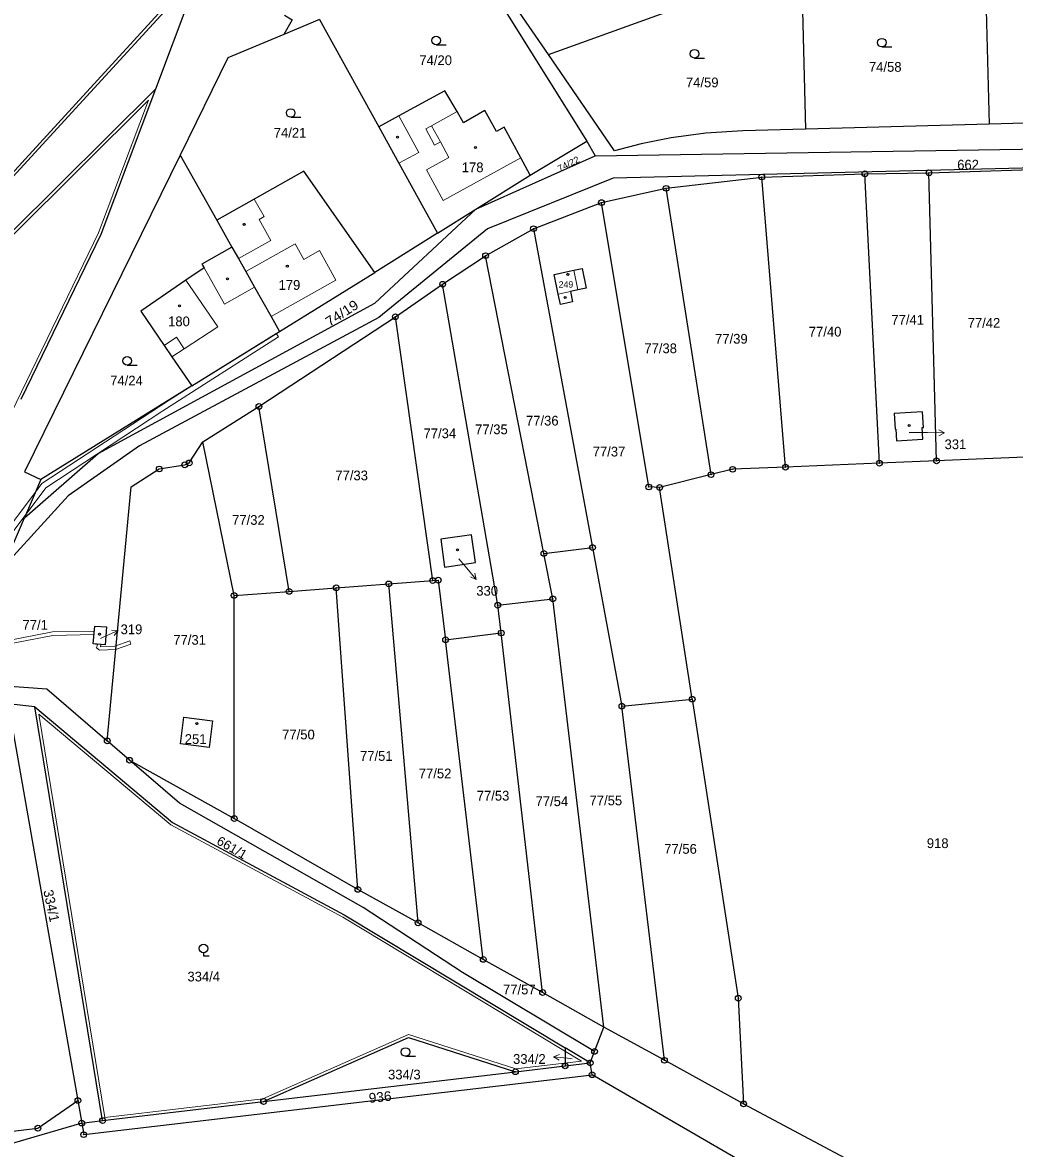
# Model space of a CAD drawing. Extents: x -758887 to -754328, y -1031688 to -1029144.
# Drawn here: x -756593.9 to -756420.8, y -1030846 to -1030649.6 of the extents above; entities that cross this region are included whole.
import ezdxf
from ezdxf.enums import TextEntityAlignment as Align

# ---------------------------------------------------------------- set-up
doc = ezdxf.new("R2010")
doc.units = 0
doc.header["$LTSCALE"] = 0.68
for name, color, linetype, lineweight in [('1', 7, 'Continuous', 25), ('13', 7, 'Continuous', 13), ('3', 7, 'Continuous', 25), ('4', 7, 'Continuous', 13), ('5', 7, 'Continuous', 25), ('7', 7, 'Continuous', 13), ('8', 7, 'Continuous', 25)]:
    doc.layers.add(name, color=color, linetype=linetype, lineweight=lineweight)
doc.layers.add('2', color=7, linetype='Continuous')

msp = doc.modelspace()

# ---------------------------------------------------------------- linework, layer by layer
at = {"layer": '1'}
for p, q in [((-756426.06, -1030637.12), (-756425.23, -1030667.33)), ((-756457.99, -1030641.12), (-756457.25, -1030668.21)), ((-756570.62, -1030661.18), (-756563.65, -1030642.64)), ((-756542.09, -1030649.11), (-756548.27, -1030651.69)), ((-756542.09, -1030649.11), (-756531.73, -1030667.81)), ((-756505.29, -1030676.26), (-756495.42, -1030670.29)), ((-756514.77, -1030682.19), (-756493.95, -1030672.9)), ((-756460.76, -1030727.18), (-756464.91, -1030676.57)), ((-756444.38, -1030726.5), (-756446.91, -1030676.02)), ((-756434.41, -1030726.09), (-756435.73, -1030675.84)), ((-756473.76, -1030728.49), (-756481.59, -1030678.54)), ((-756521.45, -1030686.37), (-756532.44, -1030693.24)), ((-756504.73, -1030685.58), (-756494.43, -1030741.22)), ((-756502.92, -1030742.22), (-756513.09, -1030690.29)), ((-756549.05, -1030703.54), (-756532.44, -1030693.24)), ((-756510.97, -1030751.27), (-756520.58, -1030695.27)), ((-756564.31, -1030713), (-756549.05, -1030703.54)), ((-756564.31, -1030713), (-756590.69, -1030729.36)), ((-756562.42, -1030722.77), (-756552.63, -1030716.6)), ((-756556.96, -1030749.57), (-756562.42, -1030722.77)), ((-756444.38, -1030726.5), (-756460.76, -1030727.18)), ((-756590.69, -1030729.36), (-756593.53, -1030736.02)), ((-756579.1, -1030774.93), (-756574.95, -1030730.63)), ((-756597.17, -1030744.56), (-756593.53, -1030736.02)), ((-756502.92, -1030742.22), (-756494.43, -1030741.22)), ((-756494.43, -1030741.22), (-756489.31, -1030768.85)), ((-756539.14, -1030748.23), (-756529.98, -1030747.55)), ((-756524.87, -1030806.67), (-756529.98, -1030747.55)), ((-756547.36, -1030748.85), (-756539.14, -1030748.23)), ((-756535.37, -1030800.83), (-756539.14, -1030748.23)), ((-756492.45, -1030824.84), (-756501.36, -1030750.16)), ((-756513.49, -1030813.05), (-756520.07, -1030757.28)), ((-756503.14, -1030818.82), (-756510.35, -1030756.11)), ((-756596.41, -1030768.46), (-756584.22, -1030837.68)), ((-756591.74, -1030769.01), (-756596.41, -1030768.46)), ((-756579.91, -1030841.16), (-756591.74, -1030769.01)), ((-756481.89, -1030830.65), (-756489.31, -1030768.85)), ((-756575.2, -1030778.3), (-756579.1, -1030774.93)), ((-756535.37, -1030800.83), (-756556.93, -1030788.48)), ((-756524.87, -1030806.67), (-756535.37, -1030800.83)), ((-756513.49, -1030813.05), (-756524.87, -1030806.67)), ((-756494.84, -1030831.1), (-756499.23, -1030828.46)), ((-756499.23, -1030828.46), (-756499.2, -1030831.62)), ((-756494.84, -1030831.1), (-756494.08, -1030829.1)), ((-756507.88, -1030832.64), (-756499.2, -1030831.62)), ((-756499.2, -1030831.62), (-756494.84, -1030831.1)), ((-756551.82, -1030837.84), (-756507.88, -1030832.64)), ((-756468.05, -1030848.51), (-756494.5, -1030833.17)), ((-756579.91, -1030841.16), (-756551.82, -1030837.84)), ((-756468.07, -1030838.25), (-756377.14, -1030886.55))]:
    msp.add_line(p, q, dxfattribs=at)
for points in [[(-756312.59, -1030555.25), (-756315.52, -1030551.79), (-756381.49, -1030591.35), (-756401.18, -1030595.86), (-756437.11, -1030607.98), (-756464.98, -1030615.64), (-756516.89, -1030636.06), (-756515.63, -1030638.06), (-756495.42, -1030670.29), (-756493.95, -1030672.9)], [(-756502.13, -1030655.2), (-756514.55, -1030637.12), (-756496.93, -1030629.62), (-756473.6, -1030620.91)], [(-756502.13, -1030655.2), (-756465.93, -1030642.12), (-756473.6, -1030620.91)], [(-756622.25, -1030695.77), (-756617.82, -1030689.9), (-756596.84, -1030677.93), (-756567.17, -1030645.53)], [(-756548.16, -1030648.36), (-756546.86, -1030649.18), (-756548.27, -1030651.69)], [(-756493.95, -1030672.9), (-756371.38, -1030670.94), (-756309.15, -1030664.75), (-756283.71, -1030651.34)], [(-756548.27, -1030651.69), (-756558.05, -1030655.77), (-756566.39, -1030672.73), (-756559.98, -1030684.11)], [(-756282.9, -1030655.55), (-756308.06, -1030668.02), (-756379, -1030674.01), (-756490.83, -1030676.79), (-756512.76, -1030685.59), (-756531.71, -1030701.08), (-756573.47, -1030723.47), (-756585.94, -1030732.18), (-756597.17, -1030744.56)], [(-756457.25, -1030668.21), (-756468.21, -1030668.51), (-756474.65, -1030668.92), (-756480.7, -1030669.74), (-756485.92, -1030670.8), (-756490.57, -1030672.03), (-756502.13, -1030655.2)], [(-756300.24, -1030658.53), (-756307.58, -1030661.72), (-756313.13, -1030663.29), (-756320.52, -1030664.4), (-756327.16, -1030664.64), (-756346.44, -1030665.17), (-756369.47, -1030665.8), (-756396.2, -1030666.53), (-756425.23, -1030667.33), (-756457.25, -1030668.21)], [(-756570.62, -1030661.18), (-756595.91, -1030686.32), (-756615.43, -1030693.08), (-756624.55, -1030704.88), (-756623.32, -1030705.86)], [(-756594.09, -1030715.3), (-756580.15, -1030686.52), (-756570.62, -1030661.18)], [(-756505.29, -1030676.26), (-756506.93, -1030673.25), (-756509.87, -1030667.89), (-756511.21, -1030668.63), (-756513.21, -1030664.99), (-756516.96, -1030667.14), (-756518.04, -1030665.15), (-756520.2, -1030661.55), (-756528.2, -1030665.9), (-756531.73, -1030667.81)], [(-756531.73, -1030667.81), (-756528.22, -1030674.15), (-756521.45, -1030686.37), (-756514.77, -1030682.19), (-756505.29, -1030676.26)], [(-756566.39, -1030672.73), (-756593.55, -1030728.01), (-756590.69, -1030729.36)], [(-756552.63, -1030716.6), (-756528.83, -1030700.94), (-756520.58, -1030695.27), (-756513.09, -1030690.29), (-756504.73, -1030685.58), (-756492.87, -1030681.04), (-756481.59, -1030678.54), (-756464.91, -1030676.57), (-756446.91, -1030676.02), (-756435.73, -1030675.84), (-756417.72, -1030675.24), (-756398.55, -1030674.79), (-756378.46, -1030674.21), (-756358.59, -1030673.95), (-756338.15, -1030673.21), (-756319.23, -1030673.82)], [(-756532.44, -1030693.24), (-756544.82, -1030675.57), (-756553.45, -1030680.43), (-756559.98, -1030684.11), (-756557.34, -1030688.81)], [(-756482.72, -1030730.71), (-756484.63, -1030730.64), (-756492.87, -1030681.04)], [(-756593.53, -1030736.02), (-756580.68, -1030724.81), (-756532.4, -1030698.57), (-756514.77, -1030682.19)], [(-756557.34, -1030688.81), (-756562.57, -1030691.75), (-756562.19, -1030692.42), (-756565.37, -1030694.59), (-756573.24, -1030699.98), (-756569.15, -1030705.95), (-756567.8, -1030707.92), (-756564.31, -1030713)], [(-756557.34, -1030688.81), (-756556.21, -1030690.81), (-756554.94, -1030693.08), (-756553.41, -1030695.78), (-756550.52, -1030700.93), (-756549.05, -1030703.54)], [(-756529.98, -1030747.55), (-756522.31, -1030746.97), (-756528.83, -1030700.94)], [(-756556.96, -1030749.57), (-756547.36, -1030748.85), (-756552.63, -1030716.6)], [(-756574.95, -1030730.63), (-756570.02, -1030727.5), (-756565.58, -1030726.78), (-756564.78, -1030726.44), (-756562.42, -1030722.77)], [(-756415.17, -1030725.25), (-756416.23, -1030725.34), (-756434.41, -1030726.09), (-756444.38, -1030726.5)], [(-756460.76, -1030727.18), (-756469.98, -1030727.56), (-756473.76, -1030728.49), (-756482.72, -1030730.71)], [(-756489.31, -1030768.85), (-756477.04, -1030767.65), (-756482.72, -1030730.71)], [(-756510.97, -1030751.27), (-756501.36, -1030750.16), (-756502.92, -1030742.22)], [(-756522.31, -1030746.97), (-756521.34, -1030746.9), (-756520.07, -1030757.28)], [(-756575.2, -1030778.3), (-756556.93, -1030788.48), (-756556.96, -1030749.57)], [(-756520.07, -1030757.28), (-756510.35, -1030756.11), (-756510.97, -1030751.27)], [(-756605.74, -1030764.66), (-756589.65, -1030765.83), (-756579.1, -1030774.93)], [(-756591.74, -1030769.01), (-756567.74, -1030789.14), (-756537.76, -1030805.25), (-756499.23, -1030828.46)], [(-756477.04, -1030767.65), (-756469.01, -1030819.82), (-756468.07, -1030838.25)], [(-756494.08, -1030829.1), (-756517.09, -1030815.34), (-756534.42, -1030804.01), (-756566.5, -1030785.8), (-756575.2, -1030778.3)], [(-756494.08, -1030829.1), (-756492.45, -1030824.84), (-756503.14, -1030818.82), (-756513.49, -1030813.05)], [(-756468.07, -1030838.25), (-756481.89, -1030830.65), (-756492.45, -1030824.84)], [(-756551.82, -1030837.84), (-756526.53, -1030826.65), (-756507.88, -1030832.64)], [(-756583.54, -1030841.59), (-756583.21, -1030843.62), (-756494.5, -1030833.17), (-756494.84, -1030831.1)], [(-756614.71, -1030845.27), (-756591.19, -1030842.49), (-756584.22, -1030837.68)], [(-756584.22, -1030837.68), (-756583.54, -1030841.59), (-756579.91, -1030841.16)], [(-756583.54, -1030841.59), (-756604.14, -1030847.6), (-756617.85, -1030857.11), (-756621.79, -1030861.59), (-756483.51, -1030902.61)]]:
    msp.add_lwpolyline(points, dxfattribs=at)
for points in [[(-756496.98, -1030696.27), (-756498.26, -1030696.56), (-756497.9, -1030698.32), (-756500.04, -1030698.8), (-756500.4, -1030697.03), (-756501.11, -1030693.56), (-756497.72, -1030692.83), (-756496.26, -1030692.51), (-756495.55, -1030695.95)], [(-756436.82, -1030722.3), (-756436.92, -1030720.28), (-756436.7, -1030720.27), (-756436.88, -1030717.52), (-756441.8, -1030717.8), (-756441.64, -1030720.54), (-756441.51, -1030720.54), (-756441.39, -1030722.59)], [(-756515.56, -1030738.96), (-756520.92, -1030739.74), (-756520.23, -1030744.6), (-756514.82, -1030743.82)], [(-756581.53, -1030758.02), (-756581.27, -1030754.91), (-756579.23, -1030755.06), (-756579.47, -1030758.15)], [(-756561.33, -1030776.08), (-756566.29, -1030775.42), (-756565.72, -1030770.81), (-756560.76, -1030771.42)]]:
    msp.add_lwpolyline(points, close=True, dxfattribs=at)
at = {"layer": '13'}
for points in [[(-756605.47, -1030751.56), (-756593.25, -1030735.36), (-756589.79, -1030730.78), (-756569.38, -1030717.35), (-756549.22, -1030704.47), (-756549.6, -1030703.88), (-756564.31, -1030713), (-756568.3, -1030715.47), (-756590.49, -1030730.04), (-756591.62, -1030731.54), (-756604.84, -1030749.06)], [(-756603.5, -1030759.41), (-756588.59, -1030756.52), (-756581.41, -1030756.38), (-756581.53, -1030758.02), (-756581.27, -1030754.91), (-756581.36, -1030755.78), (-756588.65, -1030755.92), (-756603.22, -1030758.75)]]:
    msp.add_lwpolyline(points, dxfattribs=at)
msp.add_lwpolyline([(-756581.53, -1030758.02), (-756580.8, -1030758.09), (-756580.96, -1030758.68), (-756580.47, -1030759.13), (-756577.66, -1030758.99), (-756574.98, -1030758.07), (-756575.18, -1030757.5), (-756577.78, -1030758.39), (-756580.25, -1030758.51), (-756580.19, -1030758.13), (-756579.47, -1030758.15)], close=True, dxfattribs=at)
at = {"layer": '3'}
for p, q in [((-756521.693, -1030653.5), (-756519.943, -1030653.5)), ((-756443.943, -1030653.88), (-756442.193, -1030653.88)), ((-756476.643, -1030655.81), (-756474.893, -1030655.81)), ((-756547.093, -1030666.15), (-756545.343, -1030666.15)), ((-756575.633, -1030709.38), (-756573.883, -1030709.38)), ((-756527.053, -1030829.95), (-756525.303, -1030829.95))]:
    msp.add_line(p, q, dxfattribs=at)
msp.add_lwpolyline([(-756562.32, -1030811.912), (-756562.32, -1030812.41), (-756561.319, -1030812.41)], dxfattribs=at)
for centre in [(-756521.6929, -1030652.7498), (-756443.9429, -1030653.1298), (-756476.6429, -1030655.0598), (-756547.0929, -1030665.3998), (-756575.6329, -1030708.6298), (-756562.3193, -1030811.1609), (-756527.0529, -1030829.1998)]:
    msp.add_circle(centre, 0.75, dxfattribs=at)
at = {"layer": '4'}
for p, q in [((-756597.16, -1030677.54), (-756568.24, -1030645.96)), ((-756595.64, -1030686.75), (-756571.9, -1030663.15)), ((-756580.61, -1030686.32), (-756571.9, -1030663.15)), ((-756524.75, -1030672.27), (-756528.2, -1030665.9)), ((-756522, -1030670.99), (-756523.51, -1030668.15)), ((-756520.97, -1030670.43), (-756522.52, -1030667.62)), ((-756528.22, -1030674.15), (-756524.75, -1030672.27)), ((-756523.42, -1030675.32), (-756519.49, -1030673.17)), ((-756551.73, -1030683.48), (-756553.45, -1030680.43)), ((-756597.65, -1030721.5), (-756580.61, -1030686.32)), ((-756556.21, -1030690.81), (-756550.55, -1030687.63)), ((-756554.94, -1030693.08), (-756546.31, -1030688.23)), ((-756546.31, -1030688.23), (-756544.79, -1030690.93)), ((-756544.79, -1030690.93), (-756542.08, -1030689.41)), ((-756542.08, -1030689.41), (-756539.19, -1030694.55)), ((-756562.19, -1030692.42), (-756558.64, -1030698.73)), ((-756497.72, -1030692.83), (-756496.98, -1030696.27)), ((-756559.8, -1030702.73), (-756565.37, -1030694.59)), ((-756539.19, -1030694.55), (-756550.52, -1030700.93)), ((-756558.64, -1030698.73), (-756553.41, -1030695.78)), ((-756500.4, -1030697.03), (-756498.26, -1030696.56)), ((-756569.15, -1030705.95), (-756567.03, -1030704.5)), ((-756565.65, -1030706.52), (-756559.8, -1030702.73)), ((-756568.02, -1030789.56), (-756591.03, -1030770.26)), ((-756579.49, -1030840.61), (-756591.03, -1030770.26)), ((-756526.56, -1030826.12), (-756551.95, -1030837.35)), ((-756507.83, -1030832.13), (-756526.56, -1030826.12)), ((-756579.49, -1030840.61), (-756551.95, -1030837.35))]:
    msp.add_line(p, q, dxfattribs=at)
for points in [[(-756523.51, -1030668.15), (-756522.52, -1030667.62), (-756518.04, -1030665.15)], [(-756519.49, -1030673.17), (-756520.97, -1030670.43), (-756522, -1030670.99)], [(-756523.42, -1030675.32), (-756520.49, -1030680.67), (-756506.93, -1030673.25)], [(-756550.55, -1030687.63), (-756552.6, -1030683.97), (-756551.73, -1030683.48)], [(-756567.8, -1030707.92), (-756565.65, -1030706.52), (-756567.03, -1030704.5)], [(-756507.83, -1030832.13), (-756496.35, -1030830.78), (-756538.01, -1030805.68), (-756568.02, -1030789.56)]]:
    msp.add_lwpolyline(points, dxfattribs=at)
at = {"layer": '5'}
for centre in [(-756528.4768, -1030669.6392), (-756514.8568, -1030671.4192), (-756555.1868, -1030684.8292), (-756547.6768, -1030692.1092), (-756558.1268, -1030694.3392), (-756498.7468, -1030693.5492), (-756499.1968, -1030697.5692), (-756566.4868, -1030699.0492), (-756439.2068, -1030719.9292), (-756517.9668, -1030741.6192), (-756580.4368, -1030756.3392), (-756563.4568, -1030771.9192)]:
    msp.add_circle(centre, 0.175, dxfattribs=at)
at = {"layer": '7'}
for p, q in [((-756433.009, -1030721.212), (-756434.002, -1030720.694)), ((-756514.711, -1030746.769), (-756514.971, -1030745.68)), ((-756577.21, -1030755.652), (-756578.329, -1030755.621)), ((-756501.215, -1030830.046), (-756500.271, -1030830.649))]:
    msp.add_line(p, q, dxfattribs=at)
for points in [[(-756439.18, -1030721.11), (-756436.01, -1030721.16), (-756433.009, -1030721.212), (-756434.02, -1030721.696)], [(-756517.73, -1030743.17), (-756516.64, -1030744.47), (-756514.711, -1030746.769), (-756515.738, -1030746.324)], [(-756580.25, -1030757.07), (-756579.93, -1030756.92), (-756577.21, -1030755.652), (-756577.906, -1030756.529)], [(-756498.01, -1030830.39), (-756498.23, -1030830.36), (-756501.215, -1030830.046), (-756500.166, -1030829.653)]]:
    msp.add_lwpolyline(points, dxfattribs=at)
at = {"layer": '8'}
for centre, radius in [((-756464.91, -1030676.5699), 0.5), ((-756464.91, -1030676.5699), 0.0303), ((-756446.91, -1030676.0199), 0.5), ((-756446.91, -1030676.0199), 0.0303), ((-756435.73, -1030675.8399), 0.5), ((-756435.73, -1030675.8399), 0.0303), ((-756481.59, -1030678.5399), 0.5), ((-756481.59, -1030678.5399), 0.0303), ((-756492.87, -1030681.0399), 0.5), ((-756492.87, -1030681.0399), 0.0303), ((-756504.73, -1030685.5799), 0.5), ((-756504.73, -1030685.5799), 0.0303), ((-756513.09, -1030690.2899), 0.5), ((-756513.09, -1030690.2899), 0.0303), ((-756520.58, -1030695.2699), 0.5), ((-756520.58, -1030695.2699), 0.0303), ((-756528.83, -1030700.9399), 0.5), ((-756528.83, -1030700.9399), 0.0303), ((-756552.63, -1030716.5999), 0.5), ((-756552.63, -1030716.5999), 0.0303), ((-756565.58, -1030726.7799), 0.5), ((-756564.78, -1030726.4399), 0.5), ((-756444.38, -1030726.4999), 0.5), ((-756434.41, -1030726.0899), 0.5), ((-756434.41, -1030726.0899), 0.0303), ((-756570.02, -1030727.4999), 0.5), ((-756570.02, -1030727.4999), 0.0303), ((-756565.58, -1030726.7799), 0.0303), ((-756564.78, -1030726.4399), 0.0303), ((-756473.76, -1030728.4899), 0.5), ((-756469.98, -1030727.5599), 0.5), ((-756469.98, -1030727.5599), 0.0303), ((-756460.76, -1030727.1799), 0.5), ((-756460.76, -1030727.1799), 0.0303), ((-756444.38, -1030726.4999), 0.0303), ((-756484.63, -1030730.6399), 0.5), ((-756482.72, -1030730.7099), 0.5), ((-756473.76, -1030728.4899), 0.0303), ((-756484.63, -1030730.6399), 0.0303), ((-756482.72, -1030730.7099), 0.0303), ((-756502.92, -1030742.2199), 0.5), ((-756494.43, -1030741.2199), 0.5), ((-756494.43, -1030741.2199), 0.0303), ((-756502.92, -1030742.2199), 0.0303), ((-756539.14, -1030748.2299), 0.5), ((-756529.98, -1030747.5499), 0.5), ((-756529.98, -1030747.5499), 0.0303), ((-756522.31, -1030746.9699), 0.5), ((-756522.31, -1030746.9699), 0.0303), ((-756521.34, -1030746.8999), 0.5), ((-756521.34, -1030746.8999), 0.0303), ((-756556.96, -1030749.5699), 0.5), ((-756556.96, -1030749.5699), 0.0303), ((-756547.36, -1030748.8499), 0.5), ((-756547.36, -1030748.8499), 0.0303), ((-756539.14, -1030748.2299), 0.0303), ((-756501.36, -1030750.1599), 0.5), ((-756510.97, -1030751.2699), 0.5), ((-756510.97, -1030751.2699), 0.0303), ((-756501.36, -1030750.1599), 0.0303), ((-756510.35, -1030756.1099), 0.5), ((-756520.07, -1030757.2799), 0.5), ((-756520.07, -1030757.2799), 0.0303), ((-756510.35, -1030756.1099), 0.0303), ((-756477.04, -1030767.6499), 0.5), ((-756489.31, -1030768.8499), 0.5), ((-756489.31, -1030768.8499), 0.0303), ((-756477.04, -1030767.6499), 0.0303), ((-756579.1, -1030774.9299), 0.5), ((-756579.1, -1030774.9299), 0.0303), ((-756575.2, -1030778.2999), 0.5), ((-756575.2, -1030778.2999), 0.0303), ((-756556.93, -1030788.4799), 0.5), ((-756556.93, -1030788.4799), 0.0303), ((-756535.37, -1030800.8299), 0.5), ((-756535.37, -1030800.8299), 0.0303), ((-756524.87, -1030806.6699), 0.5), ((-756524.87, -1030806.6699), 0.0303), ((-756513.49, -1030813.0499), 0.5), ((-756513.49, -1030813.0499), 0.0303), ((-756503.14, -1030818.8199), 0.5), ((-756503.14, -1030818.8199), 0.0303), ((-756469.01, -1030819.8199), 0.5), ((-756469.01, -1030819.8199), 0.0303), ((-756494.08, -1030829.0999), 0.5), ((-756494.08, -1030829.0999), 0.0303), ((-756481.89, -1030830.6499), 0.5), ((-756507.88, -1030832.6399), 0.5), ((-756499.2, -1030831.6199), 0.5), ((-756499.2, -1030831.6199), 0.0303), ((-756494.84, -1030831.0999), 0.5), ((-756494.84, -1030831.0999), 0.0303), ((-756481.89, -1030830.6499), 0.0303), ((-756507.88, -1030832.6399), 0.0303), ((-756494.5, -1030833.1699), 0.5), ((-756494.5, -1030833.1699), 0.0303), ((-756584.22, -1030837.6799), 0.5), ((-756584.22, -1030837.6799), 0.0303), ((-756551.82, -1030837.8399), 0.5), ((-756551.82, -1030837.8399), 0.0303), ((-756468.07, -1030838.2499), 0.5), ((-756468.07, -1030838.2499), 0.0303), ((-756591.19, -1030842.4899), 0.5), ((-756583.54, -1030841.5899), 0.5), ((-756583.54, -1030841.5899), 0.0303), ((-756579.91, -1030841.1599), 0.5), ((-756579.91, -1030841.1599), 0.0303), ((-756591.19, -1030842.4899), 0.0303), ((-756583.21, -1030843.6199), 0.5), ((-756583.21, -1030843.6199), 0.0303)]:
    msp.add_circle(centre, radius, dxfattribs=at)

# ---------------------------------------------------------------- texts
at = {"layer": '2'}
for s, height, p in [('74/20', 1.7, (-756521.8, -1030657.05)), ('74/58', 1.7, (-756443.36, -1030658.21)), ('74/59', 1.7, (-756475.29, -1030660.92)), ('74/21', 1.7, (-756547.2, -1030669.7)), ('178', 1.7, (-756515.349, -1030675.73)), ('662', 1.7, (-756428.909, -1030675.27)), ('179', 1.7, (-756547.309, -1030696.25)), ('249', 1.14, (-756499.07, -1030695.88)), ('180', 1.7, (-756566.579, -1030702.6)), ('74/24', 1.7, (-756575.74, -1030712.93)), ('77/1', 1.7, (-756591.67, -1030755.55)), ('319', 1.7, (-756574.869, -1030756.32)), ('251', 1.7, (-756563.679, -1030775.46)), ('918', 1.7, (-756434.209, -1030793.626)), ('334/4', 1.7, (-756562.26, -1030816.89)), ('334/2', 1.7, (-756505.45, -1030831.27)), ('334/3', 1.7, (-756527.26, -1030833.98))]:
    msp.add_text(s, height=height, dxfattribs=at).set_placement(p, align=Align.CENTER)
for s, height, rotation, width, p in [('74/22', 1.14, 27, 1.05, (-756498.3683, -1030674.7997)), ('74/19', 1.7, 33, 1.1, (-756537.6984, -1030701.0221)), ('661/1', 1.6, 330, 1.05, (-756557.7325, -1030794.2463)), ('936', 1.7, 6, 1.05, (-756531.4018, -1030837.8924))]:
    msp.add_text(s, height=height, rotation=rotation, dxfattribs=dict(at, width=width)).set_placement(p, align=Align.CENTER)
for s, p in [('77/41', (-756442.29, -1030702.32)), ('77/40', (-756456.7, -1030704.4)), ('77/42', (-756428.98, -1030702.87)), ('77/39', (-756473.05, -1030705.64)), ('77/38', (-756485.39, -1030707.3)), ('77/36', (-756506.04, -1030719.92)), ('77/34', (-756523.91, -1030722.13)), ('77/35', (-756514.91, -1030721.44)), ('331', (-756433.01, -1030724.043)), ('77/37', (-756494.4, -1030725.32)), ('77/33', (-756539.3, -1030729.48)), ('77/32', (-756557.31, -1030737.24)), ('330', (-756514.71, -1030749.603)), ('77/31', (-756567.57, -1030758.16)), ('77/50', (-756548.58, -1030774.67)), ('77/51', (-756535, -1030778.41)), ('77/52', (-756524.74, -1030781.46)), ('77/53', (-756514.63, -1030785.34)), ('77/54', (-756504.37, -1030786.31)), ('77/55', (-756494.95, -1030786.17)), ('77/56', (-756481.92, -1030794.62)), ('77/57', (-756510.05, -1030819.15))]:
    msp.add_text(s, height=1.7, dxfattribs=at).set_placement(p)
msp.add_text('334/1', height=1.7, rotation=282, dxfattribs=at).set_placement((-756589.6663, -1030803.8838), align=Align.CENTER)

doc.saveas('drawing.dxf')
